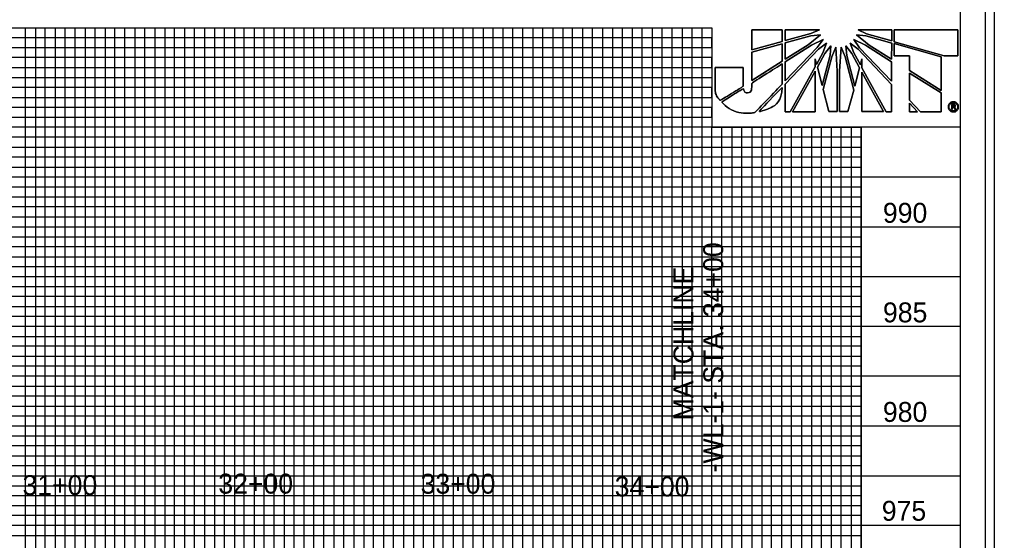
# Model space of a CAD drawing. Extents: x 0 to 2694, y -1 to 1501.
# Drawn here: x 2.017 to 2.833, y 0.45 to 0.886 of the extents above; entities that cross this region are included whole.
import ezdxf

# ---------------------------------------------------------------- set-up
doc = ezdxf.new("R2010")
doc.units = 0
for name, color, linetype in [('11 x 17 Ledger Page CELL', 7, 'Continuous'), ('8 1I2 x 11 Letter Page CELL', 7, 'Continuous'), ('Air Release (M2) CELL', 7, 'Continuous'), ('COGO Default Point Elevation', 7, 'Continuous'), ('Exist Utilities Sanitary Sewer Clean-Out CELL', 7, 'Continuous'), ('P_UTL_Water', 7, 'Continuous')]:
    doc.layers.add(name, color=color, linetype=linetype)

# ---------------------------------------------------------------- blocks, each defined once
blk = doc.blocks.new('block 2_1')
at = {"layer": '8 1I2 x 11 Letter Page CELL'}
for p, q in [((0.10682, 0.1325), (0.10682, 0.14026)), ((0.10682, 0.14026), (0.11852, 0.14026)), ((0.11852, 0.14026), (0.11852, 0.13575)), ((0.11973, 0.13613), (0.11973, 0.14032)), ((0.11973, 0.14032), (0.1329, 0.14032)), ((0.1329, 0.14032), (0.12954, 0.13884)), ((0.15109, 0.13878), (0.14781, 0.14032)), ((0.14781, 0.14032), (0.16078, 0.14026)), ((0.16078, 0.14026), (0.16078, 0.13606)), ((0.16169, 0.1358), (0.16169, 0.14032)), ((0.16169, 0.14032), (0.18629, 0.14032)), ((0.18629, 0.14032), (0.18629, 0.13024)), ((0.11852, 0.13575), (0.10682, 0.1325)), ((0.12954, 0.13884), (0.11973, 0.13613)), ((0.11973, 0.13523), (0.12954, 0.13793)), ((0.13337, 0.13839), (0.12852, 0.13445)), ((0.12954, 0.13793), (0.13337, 0.13839)), ((0.12987, 0.13432), (0.13433, 0.13658)), ((0.13433, 0.13658), (0.13207, 0.13341)), ((0.14613, 0.13658), (0.15065, 0.13432)), ((0.14839, 0.13335), (0.14613, 0.13658)), ((0.14715, 0.13839), (0.15076, 0.13793)), ((0.15206, 0.13438), (0.14715, 0.13839)), ((0.15076, 0.13793), (0.16078, 0.13517)), ((0.16078, 0.13606), (0.15109, 0.13878)), ((0.16169, 0.13567), (0.16169, 0.1358)), ((0.18106, 0.13024), (0.16169, 0.13567)), ((0.10682, 0.13161), (0.11852, 0.1349)), ((0.11852, 0.1349), (0.11852, 0.12812)), ((0.11973, 0.12889), (0.11973, 0.13523)), ((0.12852, 0.13445), (0.11973, 0.12889)), ((0.11973, 0.12787), (0.12987, 0.13432)), ((0.13207, 0.13341), (0.11973, 0.12057)), ((0.11973, 0.11933), (0.13257, 0.13277)), ((0.13257, 0.13277), (0.13568, 0.13517)), ((0.13568, 0.13517), (0.13425, 0.13142)), ((0.13505, 0.13115), (0.13736, 0.13412)), ((0.13736, 0.13412), (0.13704, 0.13051)), ((0.13769, 0.12986), (0.13929, 0.1336)), ((0.13929, 0.1336), (0.1398, 0.12437)), ((0.14063, 0.12437), (0.14123, 0.1336)), ((0.14123, 0.1336), (0.14277, 0.12986)), ((0.1431, 0.13412), (0.14536, 0.13115)), ((0.14348, 0.13038), (0.1431, 0.13412)), ((0.14476, 0.13517), (0.14787, 0.13277)), ((0.14619, 0.13142), (0.14476, 0.13517)), ((0.14787, 0.13277), (0.16071, 0.11922)), ((0.16071, 0.12043), (0.14839, 0.13335)), ((0.15065, 0.13432), (0.16071, 0.12793)), ((0.16071, 0.12897), (0.15206, 0.13438)), ((0.16078, 0.13517), (0.16071, 0.12897)), ((0.16169, 0.13497), (0.17982, 0.1298)), ((0.16169, 0.1349), (0.16169, 0.13497)), ((0.16169, 0.13019), (0.16169, 0.1349)), ((0.10682, 0.12071), (0.10682, 0.13161)), ((0.11852, 0.12812), (0.10682, 0.12071)), ((0.1318, 0.12696), (0.13122, 0.12908)), ((0.13122, 0.12908), (0.13122, 0.126)), ((0.13425, 0.13142), (0.1318, 0.12696)), ((0.13213, 0.12586), (0.13505, 0.13115)), ((0.13704, 0.13051), (0.134, 0.11883)), ((0.13439, 0.11721), (0.13769, 0.12986)), ((0.14277, 0.12986), (0.14613, 0.11702)), ((0.14652, 0.11856), (0.14348, 0.13038)), ((0.14536, 0.13115), (0.14839, 0.12567)), ((0.1487, 0.12677), (0.14619, 0.13142)), ((0.1493, 0.12908), (0.1487, 0.12677)), ((0.1493, 0.12567), (0.1493, 0.12908)), ((0.16071, 0.12793), (0.16071, 0.12043)), ((0.1677, 0.13019), (0.16169, 0.13019)), ((0.1677, 0.12457), (0.1677, 0.13019)), ((0.17982, 0.1298), (0.17982, 0.11688)), ((0.18629, 0.13024), (0.18106, 0.13024)), ((0.11973, 0.12057), (0.11973, 0.12787)), ((0.13122, 0.126), (0.12167, 0.10871)), ((0.12257, 0.10871), (0.13122, 0.12432)), ((0.13122, 0.12432), (0.1313, 0.10871)), ((0.134, 0.11883), (0.13213, 0.12586)), ((0.1398, 0.12437), (0.1398, 0.10877)), ((0.14063, 0.10877), (0.14063, 0.12437)), ((0.14839, 0.12567), (0.14652, 0.11856)), ((0.15864, 0.10871), (0.1493, 0.12567)), ((0.17982, 0.11688), (0.1677, 0.12457)), ((0.1493, 0.10877), (0.1493, 0.12399)), ((0.1493, 0.12399), (0.15768, 0.10877)), ((0.1677, 0.1236), (0.17982, 0.11597)), ((0.1677, 0.11314), (0.1677, 0.1236)), ((0.11973, 0.10871), (0.11973, 0.11933)), ((0.13659, 0.10877), (0.13439, 0.11721)), ((0.14613, 0.11702), (0.14387, 0.10877)), ((0.16071, 0.11922), (0.16071, 0.10871)), ((0.17189, 0.10871), (0.1677, 0.11314)), ((0.17982, 0.11597), (0.17982, 0.10871)), ((0.1677, 0.10871), (0.1677, 0.112)), ((0.1677, 0.112), (0.17073, 0.10871)), ((0.12167, 0.10871), (0.11973, 0.10871)), ((0.1313, 0.10871), (0.12257, 0.10871)), ((0.1398, 0.10877), (0.13659, 0.10877)), ((0.14387, 0.10877), (0.14063, 0.10877)), ((0.15768, 0.10877), (0.1493, 0.10877)), ((0.16071, 0.10871), (0.15864, 0.10871)), ((0.17073, 0.10871), (0.1677, 0.10871)), ((0.17982, 0.10871), (0.17189, 0.10871))]:
    blk.add_line(p, q, dxfattribs=at)
for points in [[(0.10682, 0.1325), (0.11852, 0.13575), (0.11852, 0.14026), (0.10682, 0.14026), (0.10682, 0.1325)], [(0.12954, 0.13884), (0.1329, 0.14032), (0.11973, 0.14032), (0.11973, 0.13613), (0.12954, 0.13884)], [(0.15109, 0.13878), (0.16078, 0.13606), (0.16078, 0.14026), (0.14781, 0.14032), (0.15109, 0.13878)], [(0.18629, 0.14032), (0.16169, 0.14032), (0.16169, 0.1358), (0.16169, 0.13567), (0.18106, 0.13024), (0.18629, 0.13024), (0.18629, 0.14032)], [(0.11973, 0.13523), (0.11973, 0.12889), (0.12852, 0.13445), (0.13337, 0.13839), (0.12954, 0.13793), (0.11973, 0.13523)], [(0.11973, 0.12787), (0.11973, 0.12057), (0.13207, 0.13341), (0.13433, 0.13658), (0.12987, 0.13432), (0.11973, 0.12787)], [(0.14613, 0.13658), (0.14839, 0.13335), (0.16071, 0.12043), (0.16071, 0.12793), (0.15065, 0.13432), (0.14613, 0.13658)], [(0.14715, 0.13839), (0.15206, 0.13438), (0.16071, 0.12897), (0.16078, 0.13517), (0.15076, 0.13793), (0.14715, 0.13839)], [(0.10682, 0.12071), (0.11852, 0.12812), (0.11852, 0.1349), (0.10682, 0.13161), (0.10682, 0.12071)], [(0.13568, 0.13517), (0.13257, 0.13277), (0.11973, 0.11933), (0.11973, 0.10871), (0.12167, 0.10871), (0.13122, 0.126), (0.13122, 0.12908), (0.1318, 0.12696), (0.13425, 0.13142), (0.13568, 0.13517)], [(0.13736, 0.13412), (0.13505, 0.13115), (0.13213, 0.12586), (0.134, 0.11883), (0.13704, 0.13051), (0.13736, 0.13412)], [(0.13769, 0.12986), (0.13439, 0.11721), (0.13659, 0.10877), (0.1398, 0.10877), (0.1398, 0.12437), (0.13929, 0.1336), (0.13769, 0.12986)], [(0.14123, 0.1336), (0.14063, 0.12437), (0.14063, 0.10877), (0.14387, 0.10877), (0.14613, 0.11702), (0.14277, 0.12986), (0.14123, 0.1336)], [(0.1431, 0.13412), (0.14348, 0.13038), (0.14652, 0.11856), (0.14839, 0.12567), (0.14536, 0.13115), (0.1431, 0.13412)], [(0.14476, 0.13517), (0.14619, 0.13142), (0.1487, 0.12677), (0.1493, 0.12908), (0.1493, 0.12567), (0.15864, 0.10871), (0.16071, 0.10871), (0.16071, 0.11922), (0.14787, 0.13277), (0.14476, 0.13517)], [(0.16169, 0.13497), (0.16169, 0.1349), (0.16169, 0.13019), (0.1677, 0.13019), (0.1677, 0.12457), (0.17982, 0.11688), (0.17982, 0.1298), (0.16169, 0.13497)], [(0.12257, 0.10871), (0.1313, 0.10871), (0.13122, 0.12432), (0.12257, 0.10871)], [(0.1493, 0.10877), (0.15768, 0.10877), (0.1493, 0.12399), (0.1493, 0.10877)], [(0.1677, 0.1236), (0.1677, 0.11314), (0.17189, 0.10871), (0.17982, 0.10871), (0.17982, 0.11597), (0.1677, 0.1236), (0.1677, 0.1236)], [(0.1677, 0.10871), (0.1677, 0.10871), (0.17073, 0.10871), (0.1677, 0.112), (0.1677, 0.10871)], [(0.18456, 0.11147), (0.18383, 0.11147), (0.18383, 0.10968), (0.18424, 0.10968), (0.18424, 0.11038), (0.18456, 0.11038), (0.18456, 0.1107), (0.18424, 0.1107), (0.18424, 0.11113), (0.18456, 0.11113), (0.18456, 0.11147)], [(0.18456, 0.11147), (0.18383, 0.11147), (0.18383, 0.10968), (0.18424, 0.10968), (0.18424, 0.11038), (0.18456, 0.11038)], [(0.18456, 0.1107), (0.18424, 0.1107), (0.18424, 0.11113), (0.18456, 0.11113)]]:
    blk.add_lwpolyline(points, dxfattribs=at)
for points in [[(0.10346, 0.12573), (0.10346, 0.12573), (0.09263, 0.12573), (0.09263, 0.12573), (0.09263, 0.12573), (0.09263, 0.11895), (0.09263, 0.11895), (0.09263, 0.11895), (0.09263, 0.11823), (0.09263, 0.11823), (0.09263, 0.11611), (0.09332, 0.11443), (0.09456, 0.11302), (0.09456, 0.11302), (0.10346, 0.11843), (0.10346, 0.11856), (0.10346, 0.11856), (0.10346, 0.12573), (0.10346, 0.12573)], [(0.10346, 0.12573), (0.10346, 0.12573), (0.10346, 0.11856), (0.10346, 0.11856), (0.10346, 0.11843), (0.09456, 0.11302), (0.09456, 0.11302), (0.09332, 0.11443), (0.09263, 0.11611), (0.09263, 0.11823), (0.09263, 0.11823), (0.09263, 0.11895), (0.09263, 0.11895), (0.09263, 0.11895), (0.09263, 0.12573), (0.09263, 0.12573), (0.09263, 0.12573), (0.10346, 0.12573), (0.10346, 0.12573)], [(0.10514, 0.11597), (0.10444, 0.11597), (0.10384, 0.11636), (0.10359, 0.11765), (0.10359, 0.11765), (0.09519, 0.11246), (0.09519, 0.11246), (0.09778, 0.10974), (0.10191, 0.10812), (0.10541, 0.10812), (0.10632, 0.10812), (0.10701, 0.10819), (0.10798, 0.10839), (0.10798, 0.10839), (0.11852, 0.11928), (0.11852, 0.11928), (0.11852, 0.11928), (0.11852, 0.12715), (0.11852, 0.12715), (0.11852, 0.12715), (0.10682, 0.11972), (0.10682, 0.11972), (0.10682, 0.11677), (0.1061, 0.11597), (0.10514, 0.11597)], [(0.10514, 0.11597), (0.1061, 0.11597), (0.10682, 0.11677), (0.10682, 0.11972), (0.10682, 0.11972), (0.11852, 0.12715), (0.11852, 0.12715), (0.11852, 0.12715), (0.11852, 0.11928), (0.11852, 0.11928), (0.11852, 0.11928), (0.10798, 0.10839), (0.10798, 0.10839), (0.10701, 0.10819), (0.10632, 0.10812), (0.10541, 0.10812), (0.10191, 0.10812), (0.09778, 0.10974), (0.09519, 0.11246), (0.09519, 0.11246), (0.10359, 0.11765), (0.10359, 0.11765), (0.10384, 0.11636), (0.10444, 0.11597), (0.10514, 0.11597)], [(0.11852, 0.11804), (0.11852, 0.11804), (0.1094, 0.10864), (0.1094, 0.10864), (0.11386, 0.10974), (0.11831, 0.11269), (0.11852, 0.11804)], [(0.11852, 0.11804), (0.11831, 0.11269), (0.11386, 0.10974), (0.1094, 0.10864), (0.1094, 0.10864), (0.11852, 0.11804), (0.11852, 0.11804)], [(0.18456, 0.10859), (0.18403, 0.10859), (0.18355, 0.10878), (0.18316, 0.10917), (0.18277, 0.10955), (0.18258, 0.11002), (0.18258, 0.11057), (0.18258, 0.11113), (0.18277, 0.1116), (0.18316, 0.11195), (0.18355, 0.11233), (0.18401, 0.11252), (0.18456, 0.11252), (0.18456, 0.11252), (0.18456, 0.11215), (0.18456, 0.11215), (0.18412, 0.11215), (0.18375, 0.112), (0.18344, 0.11171), (0.18313, 0.1114), (0.18297, 0.11101), (0.18297, 0.11057), (0.18297, 0.11013), (0.18313, 0.10974), (0.18344, 0.10943), (0.18375, 0.10913), (0.18412, 0.10898), (0.18456, 0.10898), (0.18456, 0.10898), (0.18456, 0.10859), (0.18456, 0.10859), (0.18456, 0.10859), (0.18456, 0.10859), (0.18456, 0.10859)], [(0.18456, 0.11252), (0.18401, 0.11252), (0.18355, 0.11233), (0.18316, 0.11195), (0.18277, 0.1116), (0.18258, 0.11113), (0.18258, 0.11057), (0.18258, 0.11002), (0.18277, 0.10955), (0.18316, 0.10917), (0.18355, 0.10878), (0.18403, 0.10859), (0.18456, 0.10859)], [(0.18456, 0.10898), (0.18412, 0.10898), (0.18375, 0.10913), (0.18344, 0.10943), (0.18313, 0.10974), (0.18297, 0.11013), (0.18297, 0.11057), (0.18297, 0.11101), (0.18313, 0.1114), (0.18344, 0.11171), (0.18375, 0.112), (0.18412, 0.11215), (0.18456, 0.11215)], [(0.18656, 0.11057), (0.18656, 0.11002), (0.18637, 0.10955), (0.18599, 0.10916), (0.1856, 0.10878), (0.18513, 0.10859), (0.18458, 0.10859), (0.18458, 0.10859), (0.18458, 0.10859), (0.18456, 0.10859), (0.18456, 0.10859), (0.18456, 0.10898), (0.18456, 0.10898), (0.18458, 0.10898), (0.18458, 0.10898), (0.18458, 0.10898), (0.18502, 0.10898), (0.18539, 0.10913), (0.1857, 0.10943), (0.18601, 0.10974), (0.18617, 0.11013), (0.18617, 0.11057), (0.18617, 0.11101), (0.18601, 0.1114), (0.1857, 0.11171), (0.18539, 0.112), (0.18502, 0.11215), (0.18456, 0.11215), (0.18456, 0.11215), (0.18456, 0.11252), (0.18456, 0.11252), (0.18512, 0.11252), (0.18559, 0.11233), (0.18598, 0.11195), (0.18637, 0.1116), (0.18656, 0.11113), (0.18656, 0.11057), (0.18656, 0.11057), (0.18656, 0.11057), (0.18656, 0.11057)], [(0.18656, 0.11057), (0.18656, 0.11113), (0.18637, 0.1116), (0.18598, 0.11195), (0.18559, 0.11233), (0.18512, 0.11252), (0.18456, 0.11252)], [(0.18456, 0.11215), (0.18502, 0.11215), (0.18539, 0.112), (0.1857, 0.11171), (0.18601, 0.1114), (0.18617, 0.11101), (0.18617, 0.11057), (0.18617, 0.11013), (0.18601, 0.10974), (0.1857, 0.10943), (0.18539, 0.10913), (0.18502, 0.10898), (0.18458, 0.10898), (0.18458, 0.10898), (0.18458, 0.10898), (0.18456, 0.10898)], [(0.18456, 0.11038), (0.18456, 0.11038), (0.18456, 0.1107), (0.18456, 0.1107), (0.18456, 0.1107), (0.18458, 0.1107), (0.18458, 0.1107), (0.18484, 0.1107), (0.18497, 0.11078), (0.18497, 0.11093), (0.18497, 0.11106), (0.18485, 0.11113), (0.18461, 0.11113), (0.18461, 0.11113), (0.18456, 0.11113), (0.18456, 0.11113), (0.18456, 0.11113), (0.18456, 0.11147), (0.18456, 0.11147), (0.18456, 0.11147), (0.18468, 0.11147), (0.18468, 0.11147), (0.18513, 0.11147), (0.18536, 0.11129), (0.18536, 0.11093), (0.18536, 0.11077), (0.18529, 0.11064), (0.18515, 0.11054), (0.18526, 0.11048), (0.18533, 0.11033), (0.18534, 0.1101), (0.18534, 0.1101), (0.18534, 0.11), (0.18534, 0.11), (0.18534, 0.11), (0.18536, 0.10994), (0.18536, 0.10994), (0.18536, 0.10994), (0.18536, 0.10987), (0.18536, 0.10987), (0.18536, 0.10987), (0.18541, 0.10968), (0.18541, 0.10968), (0.18541, 0.10968), (0.18503, 0.10968), (0.18503, 0.10968), (0.18499, 0.10978), (0.18495, 0.10987), (0.18495, 0.11), (0.18495, 0.11017), (0.18494, 0.11026), (0.18489, 0.11031), (0.18484, 0.11034), (0.18474, 0.11038), (0.18458, 0.11038), (0.18458, 0.11038), (0.18456, 0.11038), (0.18456, 0.11038)], [(0.18456, 0.11038), (0.18456, 0.11038), (0.18458, 0.11038), (0.18458, 0.11038), (0.18474, 0.11038), (0.18484, 0.11034), (0.18489, 0.11031), (0.18494, 0.11026), (0.18495, 0.11017), (0.18495, 0.11), (0.18495, 0.10987), (0.18499, 0.10978), (0.18503, 0.10968), (0.18503, 0.10968), (0.18541, 0.10968), (0.18541, 0.10968), (0.18541, 0.10968), (0.18536, 0.10987), (0.18536, 0.10987), (0.18536, 0.10987), (0.18536, 0.10994), (0.18536, 0.10994), (0.18536, 0.10994), (0.18534, 0.11), (0.18534, 0.11), (0.18534, 0.11), (0.18534, 0.1101), (0.18534, 0.1101), (0.18533, 0.11033), (0.18526, 0.11048), (0.18515, 0.11054), (0.18529, 0.11064), (0.18536, 0.11077), (0.18536, 0.11093), (0.18536, 0.11129), (0.18513, 0.11147), (0.18468, 0.11147), (0.18468, 0.11147), (0.18456, 0.11147), (0.18456, 0.11147)], [(0.18456, 0.11113), (0.18456, 0.11113), (0.18461, 0.11113), (0.18461, 0.11113), (0.18485, 0.11113), (0.18497, 0.11106), (0.18497, 0.11093), (0.18497, 0.11078), (0.18484, 0.1107), (0.18458, 0.1107), (0.18458, 0.1107), (0.18456, 0.1107), (0.18456, 0.1107)], [(0.18456, 0.10859), (0.18458, 0.10859), (0.18458, 0.10859), (0.18458, 0.10859), (0.18513, 0.10859), (0.1856, 0.10878), (0.18599, 0.10916), (0.18637, 0.10955), (0.18656, 0.11002), (0.18656, 0.11057)]]:
    blk.add_open_spline(points, degree=3, dxfattribs=at)

msp = doc.modelspace()

# ---------------------------------------------------------------- linework, layer by layer
at = {"layer": '11 x 17 Ledger Page CELL'}
for p, q in [((0.30499, 0.8375), (2.59666, 0.8375)), ((2.80499, 0.75416), (0.30499, 0.75416)), ((0.30499, 0.67083), (2.80499, 0.67083)), ((2.80499, 0.5875), (0.30499, 0.5875)), ((0.30499, 0.50416), (2.80499, 0.50416))]:
    msp.add_line(p, q, dxfattribs=at)
for points in [[(2.09666, 0.0875), (2.09666, 0.87916), (2.17999, 0.87916), (2.17999, 0.0875)], [(2.26333, 0.0875), (2.26333, 0.87916), (2.34666, 0.87916), (2.34666, 0.0875)], [(2.42999, 0.0875), (2.42999, 0.87916), (2.51333, 0.87916), (2.51333, 0.0875)], [(2.59666, 0.0875), (2.59666, 0.79583), (2.67999, 0.79583), (2.67999, 0.0875)]]:
    msp.add_lwpolyline(points, dxfattribs=at)
at = {"layer": 'COGO Default Point Elevation'}
msp.add_line((2.55479, 0.73308), (2.55499, 0.50795), dxfattribs=at)
for points in [[(0.02749, 0.00833), (2.83333, 0.00833), (2.83333, 1.83333), (0.02749, 1.83333)], [(0.04916, 0.04166), (2.82583, 0.04166), (2.82583, 1.8), (0.04916, 1.8)], [(2.80499, 1.79583), (0.30499, 1.79583), (0.30499, 0.04583), (2.80499, 0.04583)], [(0.38833, 0.87916), (2.59666, 0.87916), (2.59666, 0.79583), (2.72166, 0.79583), (2.72166, 0.0875), (0.38833, 0.0875)]]:
    msp.add_lwpolyline(points, close=True, dxfattribs=at)
at = {"layer": 'Exist Utilities Sanitary Sewer Clean-Out CELL'}
for points in [[(2.02166, 0.0875), (2.02166, 0.87916), (2.02999, 0.87916), (2.02999, 0.0875)], [(2.03833, 0.0875), (2.03833, 0.87916), (2.04666, 0.87916), (2.04666, 0.0875)], [(2.06333, 0.0875), (2.06333, 0.87916), (2.07166, 0.87916), (2.07166, 0.0875)], [(2.07999, 0.0875), (2.07999, 0.87916), (2.08833, 0.87916), (2.08833, 0.0875)], [(2.10499, 0.0875), (2.10499, 0.87916), (2.11333, 0.87916), (2.11333, 0.0875)], [(2.12166, 0.0875), (2.12166, 0.87916), (2.12999, 0.87916), (2.12999, 0.0875)], [(2.14666, 0.0875), (2.14666, 0.87916), (2.15499, 0.87916), (2.15499, 0.0875)], [(2.16333, 0.0875), (2.16333, 0.87916), (2.17166, 0.87916), (2.17166, 0.0875)], [(2.18833, 0.0875), (2.18833, 0.87916), (2.19666, 0.87916), (2.19666, 0.0875)], [(2.20499, 0.0875), (2.20499, 0.87916), (2.21333, 0.87916), (2.21333, 0.0875)], [(2.22999, 0.0875), (2.22999, 0.87916), (2.23833, 0.87916), (2.23833, 0.0875)], [(2.24666, 0.0875), (2.24666, 0.87916), (2.25499, 0.87916), (2.25499, 0.0875)], [(2.27166, 0.0875), (2.27166, 0.87916), (2.27999, 0.87916), (2.27999, 0.0875)], [(2.28833, 0.0875), (2.28833, 0.87916), (2.29666, 0.87916), (2.29666, 0.0875)], [(2.31333, 0.0875), (2.31333, 0.87916), (2.32166, 0.87916), (2.32166, 0.0875)], [(2.32999, 0.0875), (2.32999, 0.87916), (2.33833, 0.87916), (2.33833, 0.0875)], [(2.35499, 0.0875), (2.35499, 0.87916), (2.36333, 0.87916), (2.36333, 0.0875)], [(2.37166, 0.0875), (2.37166, 0.87916), (2.37999, 0.87916), (2.37999, 0.0875)], [(2.39666, 0.0875), (2.39666, 0.87916), (2.40499, 0.87916), (2.40499, 0.0875)], [(2.41333, 0.0875), (2.41333, 0.87916), (2.42166, 0.87916), (2.42166, 0.0875)], [(2.43833, 0.0875), (2.43833, 0.87916), (2.44666, 0.87916), (2.44666, 0.0875)], [(2.45499, 0.0875), (2.45499, 0.87916), (2.46333, 0.87916), (2.46333, 0.0875)], [(2.47999, 0.0875), (2.47999, 0.87916), (2.48833, 0.87916), (2.48833, 0.0875)], [(2.49666, 0.0875), (2.49666, 0.87916), (2.50499, 0.87916), (2.50499, 0.0875)], [(2.52166, 0.0875), (2.52166, 0.87916), (2.52999, 0.87916), (2.52999, 0.0875)], [(2.53833, 0.0875), (2.53833, 0.87916), (2.54666, 0.87916), (2.54666, 0.0875)], [(2.56333, 0.0875), (2.56333, 0.87916), (2.57166, 0.87916), (2.57166, 0.0875)], [(2.57999, 0.0875), (2.57999, 0.87916), (2.58833, 0.87916), (2.58833, 0.0875)], [(0.38833, 0.8625), (2.59666, 0.8625), (2.59666, 0.87083), (0.38833, 0.87083)], [(0.38833, 0.84583), (2.59666, 0.84583), (2.59666, 0.85416), (0.38833, 0.85416)], [(0.38833, 0.82083), (2.59666, 0.82083), (2.59666, 0.82916), (0.38833, 0.82916)], [(0.38833, 0.80416), (2.59666, 0.80416), (2.59666, 0.8125), (0.38833, 0.8125)], [(2.60499, 0.0875), (2.60499, 0.79583), (2.61333, 0.79583), (2.61333, 0.0875)], [(2.62166, 0.0875), (2.62166, 0.79583), (2.62999, 0.79583), (2.62999, 0.0875)], [(2.64666, 0.0875), (2.64666, 0.79583), (2.65499, 0.79583), (2.65499, 0.0875)], [(2.66333, 0.0875), (2.66333, 0.79583), (2.67166, 0.79583), (2.67166, 0.0875)], [(2.68833, 0.0875), (2.68833, 0.79583), (2.69666, 0.79583), (2.69666, 0.0875)], [(2.70499, 0.0875), (2.70499, 0.79583), (2.71333, 0.79583), (2.71333, 0.0875)], [(0.38833, 0.77916), (2.72166, 0.77916), (2.72166, 0.7875), (0.38833, 0.7875)], [(0.38833, 0.7625), (2.72166, 0.7625), (2.72166, 0.77083), (0.38833, 0.77083)], [(0.38833, 0.7375), (2.72166, 0.7375), (2.72166, 0.74583), (0.38833, 0.74583)], [(0.38833, 0.72083), (2.72166, 0.72083), (2.72166, 0.72916), (0.38833, 0.72916)], [(0.38833, 0.70416), (2.72166, 0.70416)], [(0.38833, 0.6875), (2.72166, 0.6875), (2.72166, 0.69583), (0.38833, 0.69583)], [(0.38833, 0.6625), (2.72166, 0.6625), (2.72166, 0.67916), (0.38833, 0.67916)], [(0.38833, 0.64583), (2.72166, 0.64583), (2.72166, 0.65416), (0.38833, 0.65416)], [(0.38833, 0.62083), (2.72166, 0.62083), (2.72166, 0.6375), (0.38833, 0.6375)], [(0.38833, 0.60416), (2.72166, 0.60416), (2.72166, 0.6125), (0.38833, 0.6125)], [(0.38833, 0.57916), (2.72166, 0.57916), (2.72166, 0.59583), (0.38833, 0.59583)], [(0.38833, 0.5625), (2.72166, 0.5625), (2.72166, 0.57083), (0.38833, 0.57083)], [(0.38833, 0.5375), (2.72166, 0.5375), (2.72166, 0.55416), (0.38833, 0.55416)], [(0.38833, 0.52083), (2.72166, 0.52083), (2.72166, 0.52916), (0.38833, 0.52916)], [(0.38833, 0.49583), (2.72166, 0.49583), (2.72166, 0.5125), (0.38833, 0.5125)], [(0.38833, 0.47916), (2.72166, 0.47916), (2.72166, 0.4875), (0.38833, 0.4875)], [(0.38833, 0.45416), (2.72166, 0.45416), (2.72166, 0.47083), (0.38833, 0.47083)]]:
    msp.add_lwpolyline(points, dxfattribs=at)
at = {"layer": 'P_UTL_Water'}
for points in [[(0.30499, 0.87916), (2.59666, 0.87916)], [(2.05499, 0.0875), (2.05499, 0.87916), (2.13833, 0.87916), (2.13833, 0.0875)], [(2.22166, 0.0875), (2.22166, 0.87916), (2.30499, 0.87916), (2.30499, 0.0875)], [(2.38833, 0.0875), (2.38833, 0.87916), (2.47166, 0.87916), (2.47166, 0.0875)], [(2.55499, 0.0875), (2.55499, 0.87916), (2.59666, 0.87916), (2.59666, 0.79583), (2.63833, 0.79583), (2.63833, 0.0875)], [(2.80499, 0.79583), (0.30499, 0.79583), (0.30499, 0.7125), (2.80499, 0.7125)], [(2.72166, 0.0875), (2.72166, 0.79583)], [(2.80499, 0.62916), (0.30499, 0.62916), (0.30499, 0.54583), (2.80499, 0.54583)], [(2.80499, 0.4625), (0.30499, 0.4625), (0.30499, 0.37916), (2.80499, 0.37916)]]:
    msp.add_lwpolyline(points, dxfattribs=at)

# ---------------------------------------------------------------- block references
at = {"layer": 'Air Release (M2) CELL', "xscale": 2.170686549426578, "yscale": 2.170686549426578}
msp.add_blockref('block 2_1', (2.39821, 0.57292), dxfattribs=at)

# ---------------------------------------------------------------- texts
at = {"layer": 'COGO Default Point Elevation'}
for s, p in [('990', (2.73985, 0.71591)), ('985', (2.73991, 0.63257)), ('980', (2.73985, 0.54924)), ('31+00', (2.01925, 0.48802)), ('32+00', (2.18322, 0.48923)), ('33+00', (2.35266, 0.48917)), ('34+00', (2.51522, 0.48684)), ('975', (2.73893, 0.4665))]:
    msp.add_text(s, height=0.016667, dxfattribs=at).set_placement(p)
for s, height, p in [('-WL-1- STA. 34+00', 0.0166667, (2.60615, 0.50697)), ('MATCHLINE ', 0.016667, (2.58114, 0.55044))]:
    msp.add_text(s, height=height, rotation=90.02355, dxfattribs=at).set_placement(p)

doc.saveas('drawing.dxf')
